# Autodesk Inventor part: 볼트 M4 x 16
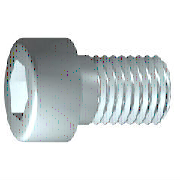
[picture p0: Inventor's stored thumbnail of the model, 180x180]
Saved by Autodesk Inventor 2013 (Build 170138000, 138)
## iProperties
IsCustomPart: 1
Created: 2012-02
Part Number: 볼트 M4 x 16
Material: 스테인리스강
Description: 6각 소켓 머리 캡 나사
Document SubType Name: Modeling
Standard: ISO 4762
Designer: mduedu
Standard Revision: Fourth edition 2004-03-01
Standards Organization: ISO
Language: ko-KR
Size Designation: M4 x 16
Categories: <MemberInstance><Categories><Category DisplayName="조임쇠" InternalName="e4da775c-781d-43d5-af7c-5136215cf5a6" Mnemonic="FSTN"><Category DisplayName="볼트" InternalN
Density: 8.08 g/cm^3
Mass: 2.70334 g
Surface Area: 3.81118 cm^2
Volume: 0.334572 cm^3
Author: mduedu
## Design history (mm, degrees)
sketch "스케치1"
  geometry: L1 (-1, 0)-(16, 0); L2 (16, 0)-(16, 2); L3 (16, 2)-(1.75, 2); L4 (1.75, 2)-(1.32, 2); L5 (1.32, 2)-(0, 2); L6 (0, 2)-(0, 3.5); L7 (0, 3.5)-(-4, 3.5); L8 (-4, 3.5)-(-4, 1.732); L9 (-4, 1.732)-(-2, 1.732); L10 (-2, 1.732)-(-1, 0); L11 (-8, 0)-(20, 0) reference; L12 (0, -0.7)-(0, 4.2) reference; L13 (1.75, 2)-(0, 2)
  constraints: 22 end point, 6 parallel, 2 collinear, 2 perpendicular, 1 horizontal, 1 point on line
  dimensions: "d1" = 14.25 distance from line of L3.end L2 (= GEL); "d2" = 0.42952 distance of L4.end L3.end (computed from GAL); "d3" = 4 distance between parallel lines of L8 L6 (= KOH); "d4" = 2 distance of L8.end L9.end (= INTI); "d5" = 60 deg angle of L10 L1; "d6" = 4 diameter of L3 L1 (= GD); "d7" = 4 diameter of L5 L1 (= BDM); "d8" = 3.4641 diameter of L9 L1 (= 1.1547 x SW); "d9" = 7 diameter of L7 L1 (= KOD); "d26" = 16 distance between parallel lines of L12 L2 (= NLG)
revolve "본체" sketch "스케치1" stored, may be unused: angle "d10" = 90 deg
sketch "스케치2"
  geometry: L1 (0, -4.9)-(0, 4.9) reference; L2 (-4.9, 0)-(4.9, 0) reference; L3 (1.732, 0)-(0.866, -1.5); L4 (0.866, -1.5)-(-0.866, -1.5); L5 (-0.866, -1.5)-(-1.732, 0); L6 (-1.732, 0)-(-0.866, 1.5); L7 (-0.866, 1.5)-(0.866, 1.5); L8 (0.866, 1.5)-(1.732, 0); 2 further points
  constraints: 12 end point, 1 coincident, 1 horizontal alignment, 1 point on line, 12 other
extrude "슬롯" join sketch "스케치2" stored distance "d11" = 10; taper "d12" = 0 deg
workplane "Work Plane1"
fillet "Fillet2" dims "d30" = 0.1 (= R)
body "Solid1"
fillet "모깎기1" dims "d17" = 0.4 (= RR)
feature "스레드" dims "d13" = 14.25 (= GEL), "d14" = 0
chamfer "모따기1" distance "d15" = 0.42941 (= -0.5 x SPD + 0.5 x GD); stored, may be unused: second distance "d16" = 0.42941 (= GUL), angle "d27" = 45 deg
other parameters: "GD" = 4 [user parameter; used in 2 equation terms], "NLG" = 16 [user parameter; used in 1 equation term], "GEL" = 14.25 [user parameter; used in 2 equation terms], "KOD" = 7 [user parameter; used in 1 equation term], "KOH" = 4 [user parameter; used in 1 equation term], "INTI" = 2 [user parameter; used in 1 equation term], "GAL" = 0.42941 (= 0.61345 x PTC) [user parameter; used in 1 equation term], "GUL" = 0.42941 (= 0.61345 x PTC) [user parameter; used in 1 equation term], "BDM" = 4 (= NND) [user parameter; used in 1 equation term], "SW" = 3 [user parameter; used in 2 equation terms], "RR" = 0.4 [user parameter; used in 1 equation term], "SPD" = 3.14117 (= NND - 1.2269 x PTC) [user parameter; used in 1 equation term], "d19" = 0, "d28" = 0, "d29" = 0, "R" = 0.1 [user parameter; used in 1 equation term], "TOA" = 30 deg [user parameter], "GD1" = 3.14117 (= THREADDIA - 1.2269 x PTC) [user parameter], "THREADDIA" = 4 [user parameter; used in 1 equation term], "FAWI" = 45 deg [user parameter], "TPU" = 14.28571 (computed from PTC) [user parameter], "PTC" = 0.7 [user parameter; used in 5 equation terms], "NND" = 4 [user parameter; used in 2 equation terms], "E0" = 3.465 (= 1.155 x SW) [user parameter]
